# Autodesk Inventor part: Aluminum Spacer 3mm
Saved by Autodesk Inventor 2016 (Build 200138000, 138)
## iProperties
Created: 2015-11
Part Number: Aluminum Spacer 3mm
Material: Generic
Document SubType Name: Modeling
Designer: John
Density: 1 g/cm^3
Appearance: Default
Author: John
Revision Number: ANY
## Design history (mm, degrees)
chamfer "Chamfer1"
body "Solid1"
